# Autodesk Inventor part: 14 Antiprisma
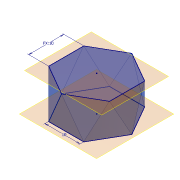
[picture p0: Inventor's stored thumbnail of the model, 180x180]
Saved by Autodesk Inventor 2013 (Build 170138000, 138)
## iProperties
Created: 2012-10
Part Number: 14 Antiprisma
Material: Allgemein
Vendor: www.inventor-faq.de
Document SubType Name: Modeling
Designer: Administrator
Manufacturer: www.inventor-faq.de
Density: 1 g/cm^3
RuleStatus: InUse
AfterDocOpen0: inventorfaq
BeforeDocSave0: inventorfaq
Author: Administrator
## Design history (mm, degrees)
sketch "Skizze1"
  geometry: L1 (-10, 0)-(-5, 8.66); L2 (-5, 8.66)-(5, 8.66); L3 (5, 8.66)-(10, 0); L4 (10, 0)-(5, -8.66); L5 (5, -8.66)-(-5, -8.66); L6 (-5, -8.66)-(-10, 0); 2 further points
  constraints: 12 end point, 1 coincident, 1 horizontal, 13 other
  dimensions: "d0" = 10 distance of L4.end L5.end
workplane "Arbeitsebene1"
sketch "Skizze2"
  geometry: L1 (0, 10)-(8.66, 5); L2 (8.66, 5)-(8.66, -5); L3 (8.66, -5)-(0, -10); L4 (0, -10)-(-8.66, -5); L5 (-8.66, -5)-(-8.66, 5); L6 (-8.66, 5)-(0, 10); 2 further points
  constraints: 12 end point, 1 coincident, 1 vertical, 13 other
  dimensions: "d2" = 10 distance of L4.end L5.end (= d0)
feature "Erhebung1" sketch "Skizze2" dims "d3" = 0, "d4" = 90 deg, "d5" = 0, "d6" = 90 deg
node "Volumenkörper1"
